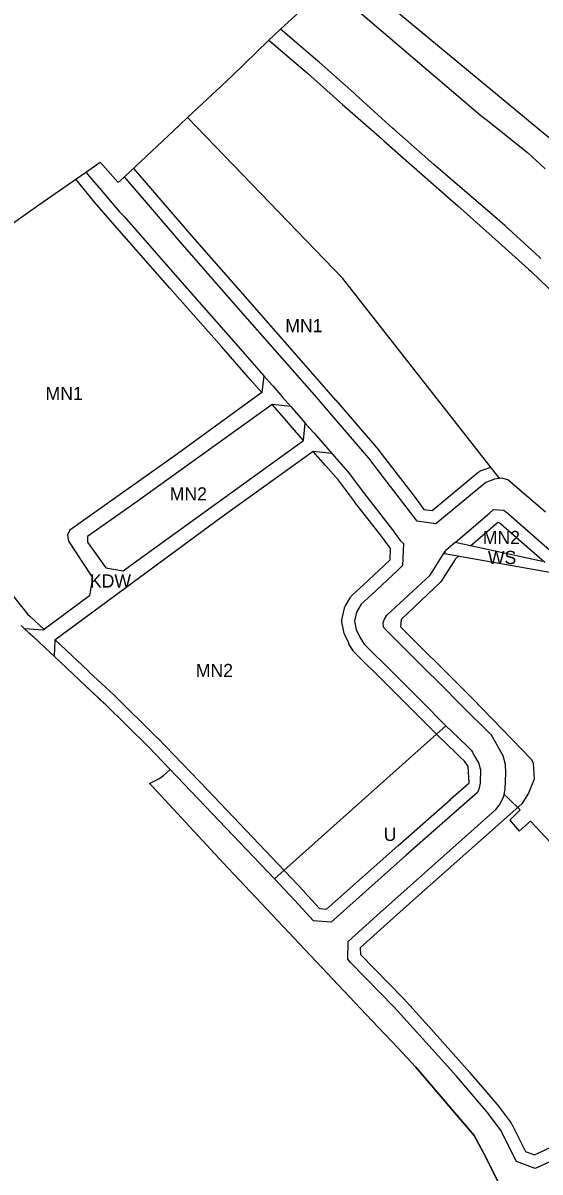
# Model space of a CAD drawing. Extents: x 7435758 to 7439981, y 5550649 to 5554049.
# Drawn here: x 7436617.4 to 7436821.5, y 5551911.1 to 5552364.7 of the extents above; entities that cross this region are included whole.
import ezdxf

# ---------------------------------------------------------------- set-up
doc = ezdxf.new("R2010")
doc.units = 0
for name, color, linetype in [('_Tereny dla których obowiązuje MPZP', 7, 'Continuous'), ('linie_rozgraniczające', 7, 'Continuous'), ('linie_zabudowy_nieprzekraczalne', 7, 'Continuous'), ('oznaczenia_przeznaczen', 7, 'Continuous')]:
    doc.layers.add(name, color=color, linetype=linetype)

msp = doc.modelspace()

# ---------------------------------------------------------------- linework, layer by layer
at = {"layer": '_Tereny dla których obowiązuje MPZP'}
for p, q in [((7436618.09, 5552125.56), (7436616.77, 5552126.8)), ((7436626.04, 5552118.11), (7436621.66, 5552122.21)), ((7436675.53, 5552070.02), (7436666.93, 5552078.97)), ((7436667.4, 5552064.42), (7436670.98, 5552066.27)), ((7436787.1, 5551935.35), (7436772.47, 5551952.52)), ((7436795.43, 5551925.58), (7436787.1, 5551935.35)), ((7436800.14, 5551917.03), (7436795.43, 5551925.58)), ((7436805.8, 5551905.51), (7436800.14, 5551917.03))]:
    msp.add_line(p, q, dxfattribs=at)
for points in [[(7436621.66, 5552122.21), (7436621.35, 5552122.5), (7436618.09, 5552125.56)], [(7436639.76, 5552105.23), (7436629.69, 5552114.68), (7436626.04, 5552118.11)], [(7436666.93, 5552078.97), (7436649.86, 5552095.77), (7436649.52, 5552096.09), (7436639.76, 5552105.23)], [(7436670.98, 5552066.27), (7436672.93, 5552067.67), (7436675.53, 5552070.02)], [(7436772.47, 5551952.52), (7436765.31, 5551960.09), (7436755.06, 5551970.94), (7436728.65, 5551998.96), (7436696.39, 5552033.17), (7436668.52, 5552063.33), (7436667.4, 5552064.42)]]:
    msp.add_lwpolyline(points, dxfattribs=at)
at = {"layer": 'linie_rozgraniczające'}
for p, q in [((7436737.83, 5552379.62), (7436798.12, 5552328.15)), ((7436719, 5552362.18), (7436734.94, 5552376.74)), ((7436828.32, 5552316.54), (7436754.67, 5552377.68)), ((7436714.41, 5552357.83), (7436719, 5552362.18)), ((7436733.68, 5552349.73), (7436719, 5552362.18)), ((7436699.7, 5552343.51), (7436714.41, 5552357.83)), ((7436714.41, 5552357.83), (7436729.68, 5552344.79)), ((7436734.36, 5552349.15), (7436733.68, 5552349.73)), ((7436748.06, 5552337.04), (7436734.36, 5552349.15)), ((7436682.42, 5552327.36), (7436699.7, 5552343.51)), ((7436729.68, 5552344.79), (7436741.13, 5552334.61)), ((7436741.13, 5552334.61), (7436743.48, 5552332.53)), ((7436748.82, 5552336.34), (7436748.06, 5552337.04)), ((7436763.28, 5552323.19), (7436748.82, 5552336.34)), ((7436743.48, 5552332.53), (7436758.9, 5552319)), ((7436679.35, 5552324.5), (7436682.42, 5552327.36)), ((7436743.6, 5552263.84), (7436682.42, 5552327.36)), ((7436798.12, 5552328.15), (7436800.78, 5552326.16)), ((7436800.78, 5552326.16), (7436816.7, 5552313.41)), ((7436674.72, 5552320.14), (7436679.35, 5552324.5)), ((7436763.78, 5552322.75), (7436763.28, 5552323.19)), ((7436779.47, 5552308.86), (7436763.78, 5552322.75)), ((7436657.44, 5552303.88), (7436674.72, 5552320.14)), ((7436758.9, 5552319), (7436759.8, 5552318.19)), ((7436759.8, 5552318.19), (7436775.04, 5552304.67)), ((7436816.7, 5552313.41), (7436823.53, 5552307.12)), ((7436642.21, 5552305.72), (7436644.29, 5552307.18)), ((7436644.29, 5552307.18), (7436647.88, 5552309.69)), ((7436647.88, 5552309.69), (7436655.06, 5552301.64)), ((7436793.58, 5552296.81), (7436779.47, 5552308.86)), ((7436623.75, 5552292.81), (7436641.77, 5552305.41)), ((7436641.77, 5552305.41), (7436642.21, 5552305.72)), ((7436642.21, 5552305.72), (7436645.04, 5552302.41)), ((7436655.06, 5552301.64), (7436657.17, 5552303.63)), ((7436657.17, 5552303.63), (7436657.44, 5552303.88)), ((7436680.33, 5552277.2), (7436657.44, 5552303.88)), ((7436775.04, 5552304.67), (7436789.02, 5552292.46)), ((7436645.04, 5552302.41), (7436648.3, 5552298.6)), ((7436648.3, 5552298.6), (7436655.54, 5552290.15)), ((7436802.59, 5552289.01), (7436793.58, 5552296.81)), ((7436601.5, 5552277.15), (7436623.75, 5552292.81)), ((7436655.54, 5552290.15), (7436657.3, 5552288.2)), ((7436789.02, 5552292.46), (7436802.61, 5552280.39)), ((7436807.58, 5552284.69), (7436802.59, 5552289.01)), ((7436657.3, 5552288.2), (7436679.16, 5552263.3)), ((7436821.22, 5552272.23), (7436807.58, 5552284.69)), ((7436802.61, 5552280.39), (7436805.12, 5552278.15)), ((7436703.17, 5552251.13), (7436680.33, 5552277.2)), ((7436805.12, 5552278.15), (7436816.98, 5552267.53)), ((7436821.84, 5552271.66), (7436821.22, 5552272.23)), ((7436816.98, 5552267.53), (7436817.87, 5552266.67)), ((7436817.87, 5552266.67), (7436831.59, 5552253.59)), ((7436679.16, 5552263.3), (7436699.47, 5552240.22)), ((7436805.24, 5552185.29), (7436743.6, 5552263.84)), ((7436733.34, 5552216.78), (7436703.17, 5552251.13)), ((7436699.47, 5552240.22), (7436712.48, 5552225.41)), ((7436712.48, 5552225.41), (7436711.75, 5552218.76)), ((7436712.48, 5552225.41), (7436715.76, 5552221.66)), ((7436715.76, 5552221.66), (7436716.11, 5552221.27)), ((7436716.11, 5552221.27), (7436719.82, 5552217.01)), ((7436711.75, 5552218.76), (7436677.43, 5552193.95)), ((7436719.82, 5552217.01), (7436723.1, 5552213.23)), ((7436737.06, 5552212.54), (7436733.34, 5552216.78)), ((7436715.79, 5552214.12), (7436661.52, 5552175.12)), ((7436723.1, 5552213.23), (7436715.79, 5552214.12)), ((7436723.1, 5552213.23), (7436725.32, 5552210.68)), ((7436753.92, 5552192.88), (7436737.06, 5552212.54)), ((7436725.32, 5552210.68), (7436728.82, 5552206.65)), ((7436728.08, 5552199.9), (7436728.82, 5552206.65)), ((7436728.82, 5552206.65), (7436729.22, 5552206.19)), ((7436729.22, 5552206.19), (7436732.16, 5552202.85)), ((7436732.16, 5552202.85), (7436736, 5552198.47)), ((7436660.97, 5552151.35), (7436728.08, 5552199.9)), ((7436736, 5552198.47), (7436739.31, 5552194.7)), ((7436677.43, 5552193.95), (7436635.93, 5552164.48)), ((7436731.96, 5552195.55), (7436696.1, 5552169.7)), ((7436739.31, 5552194.7), (7436731.96, 5552195.55)), ((7436739.31, 5552194.7), (7436745.79, 5552187.3)), ((7436759.87, 5552185.15), (7436753.92, 5552192.88)), ((7436745.79, 5552187.3), (7436752.23, 5552178.76)), ((7436767.8, 5552174.85), (7436759.87, 5552185.15)), ((7436803.46, 5552184.56), (7436800.11, 5552183.31)), ((7436805.53, 5552184.85), (7436803.46, 5552184.56)), ((7436805.53, 5552184.85), (7436805.24, 5552185.29)), ((7436806.41, 5552184.97), (7436805.53, 5552184.85)), ((7436808.74, 5552184.32), (7436806.41, 5552184.97)), ((7436800.11, 5552183.31), (7436780.41, 5552166.99)), ((7436823.61, 5552171.62), (7436808.74, 5552184.32)), ((7436752.23, 5552178.76), (7436763.23, 5552164.63)), ((7436661.52, 5552175.12), (7436642.85, 5552161.98)), ((7436773.01, 5552167.95), (7436767.8, 5552174.85)), ((7436787.94, 5552159.56), (7436801.5, 5552171.12)), ((7436801.5, 5552171.12), (7436803.17, 5552172.56)), ((7436803.17, 5552172.56), (7436807.16, 5552172.31)), ((7436807.16, 5552172.31), (7436809.23, 5552170.75)), ((7436696.1, 5552169.7), (7436630.03, 5552121.05)), ((7436780.41, 5552166.99), (7436773.01, 5552167.95)), ((7436809.23, 5552170.75), (7436828.55, 5552153.85)), ((7436635.93, 5552164.48), (7436635, 5552162.42)), ((7436635, 5552162.42), (7436635.35, 5552160.16)), ((7436642.85, 5552161.98), (7436642.95, 5552159.71)), ((7436763.23, 5552164.63), (7436766.33, 5552160.44)), ((7436635.35, 5552160.16), (7436644.23, 5552146.63)), ((7436642.95, 5552159.71), (7436650.07, 5552149.53)), ((7436766.33, 5552160.44), (7436767.54, 5552159.15)), ((7436767.54, 5552159.15), (7436767.27, 5552150.48)), ((7436787.94, 5552159.56), (7436784.31, 5552156.47)), ((7436822.42, 5552152.11), (7436787.94, 5552159.56)), ((7436778.08, 5552146.7), (7436784.08, 5552156.11)), ((7436784.08, 5552156.11), (7436783.84, 5552155.27)), ((7436783.84, 5552155.27), (7436831.22, 5552146.85)), ((7436784.31, 5552156.47), (7436784.08, 5552156.11)), ((7436650.07, 5552149.53), (7436657, 5552148.41)), ((7436657, 5552148.41), (7436660.97, 5552151.35)), ((7436765.31, 5552148.66), (7436754.95, 5552138.9)), ((7436767.27, 5552150.48), (7436765.31, 5552148.66)), ((7436644.88, 5552145.67), (7436643.71, 5552138.56)), ((7436644.23, 5552146.63), (7436644.88, 5552145.67)), ((7436760.97, 5552130.85), (7436778.08, 5552146.7)), ((7436643.71, 5552138.56), (7436625.44, 5552125.01)), ((7436750.88, 5552135.3), (7436749.07, 5552132.12)), ((7436754.95, 5552138.9), (7436750.88, 5552135.3)), ((7436749.07, 5552132.12), (7436748.31, 5552128.59)), ((7436760.13, 5552129.39), (7436760.97, 5552130.85)), ((7436618.09, 5552125.56), (7436616.77, 5552126.8)), ((7436618.09, 5552125.56), (7436616.77, 5552126.8)), ((7436621.66, 5552122.21), (7436618.09, 5552125.56)), ((7436625.44, 5552125.01), (7436618.09, 5552125.56)), ((7436748.31, 5552128.59), (7436748.96, 5552125.25)), ((7436759.53, 5552128.07), (7436760.13, 5552129.39)), ((7436759.74, 5552126.14), (7436759.53, 5552128.07)), ((7436760.83, 5552124.89), (7436759.74, 5552126.14)), ((7436626.04, 5552118.11), (7436621.66, 5552122.21)), ((7436626.04, 5552118.11), (7436621.66, 5552122.21)), ((7436630.03, 5552121.05), (7436629.69, 5552114.68)), ((7436748.96, 5552125.25), (7436750.38, 5552122.19)), ((7436750.38, 5552122.19), (7436752.05, 5552119.41)), ((7436775.75, 5552110.01), (7436760.83, 5552124.89)), ((7436629.69, 5552114.68), (7436626.04, 5552118.11)), ((7436752.05, 5552119.41), (7436763.65, 5552107.96)), ((7436639.76, 5552105.23), (7436629.69, 5552114.68)), ((7436763.65, 5552107.96), (7436774.86, 5552096.77)), ((7436782.28, 5552103.48), (7436775.75, 5552110.01)), ((7436649.86, 5552095.77), (7436639.76, 5552105.23)), ((7436790.2, 5552095.57), (7436782.28, 5552103.48)), ((7436666.93, 5552078.97), (7436649.86, 5552095.77)), ((7436774.86, 5552096.77), (7436784.37, 5552087.28)), ((7436802.37, 5552083.59), (7436790.2, 5552095.57)), ((7436761.03, 5552066.45), (7436784.37, 5552087.28)), ((7436784.37, 5552087.28), (7436786.4, 5552085.24)), ((7436786.4, 5552085.24), (7436792.76, 5552079.14)), ((7436806.91, 5552075.42), (7436802.37, 5552083.59)), ((7436686.62, 5552058.46), (7436666.93, 5552078.97)), ((7436675.53, 5552070.02), (7436666.93, 5552078.97)), ((7436792.76, 5552079.14), (7436794.29, 5552077.67)), ((7436794.29, 5552077.67), (7436794.8, 5552076.77)), ((7436794.8, 5552076.77), (7436795.27, 5552075.92)), ((7436795.27, 5552075.92), (7436795.86, 5552074.86)), ((7436795.86, 5552074.86), (7436797.31, 5552072.31)), ((7436797.31, 5552072.31), (7436797.78, 5552070.66)), ((7436807.88, 5552072.02), (7436806.91, 5552075.42)), ((7436807.98, 5552068.59), (7436807.88, 5552072.02)), ((7436797.78, 5552070.66), (7436797.97, 5552069.97)), ((7436797.97, 5552069.97), (7436797.81, 5552064.61)), ((7436807.76, 5552062.36), (7436807.98, 5552068.59)), ((7436667.4, 5552064.42), (7436670.98, 5552066.27)), ((7436716.64, 5552026.84), (7436761.03, 5552066.45)), ((7436797.37, 5552062.16), (7436796.78, 5552060.93)), ((7436797.81, 5552064.61), (7436797.37, 5552062.16)), ((7436807.27, 5552060.18), (7436807.76, 5552062.36)), ((7436716.64, 5552026.84), (7436686.62, 5552058.46)), ((7436796.78, 5552060.93), (7436789.4, 5552054.47)), ((7436805.46, 5552056.09), (7436807.03, 5552059.11)), ((7436807.03, 5552059.11), (7436807.27, 5552060.18)), ((7436807.27, 5552060.18), (7436809.01, 5552058.5)), ((7436809.01, 5552058.5), (7436813.62, 5552054.07)), ((7436756.98, 5552012.28), (7436804.1, 5552054.14)), ((7436789.4, 5552054.47), (7436768.64, 5552036.13)), ((7436804.1, 5552054.14), (7436805.46, 5552056.09)), ((7436813.62, 5552054.07), (7436809.59, 5552049.96)), ((7436809.59, 5552049.96), (7436813.22, 5552045.67)), ((7436813.22, 5552045.67), (7436817.74, 5552049.55)), ((7436817.74, 5552049.55), (7436832.43, 5552033.88)), ((7436768.64, 5552036.13), (7436739.01, 5552009.68)), ((7436724.72, 5552018.34), (7436716.64, 5552026.84)), ((7436732.02, 5552010.27), (7436724.72, 5552018.34)), ((7436745.81, 5552002.16), (7436756.98, 5552012.28)), ((7436739.01, 5552009.68), (7436732.02, 5552010.27)), ((7436728.65, 5551998.96), (7436755.06, 5551970.94)), ((7436745.58, 5551995.13), (7436745.81, 5552002.16)), ((7436746.75, 5551993.82), (7436745.58, 5551995.13)), ((7436763.86, 5551976.21), (7436746.75, 5551993.82)), ((7436773.94, 5551965.1), (7436763.86, 5551976.21)), ((7436755.06, 5551970.94), (7436765.31, 5551960.09)), ((7436778.9, 5551959.57), (7436773.94, 5551965.1)), ((7436765.31, 5551960.09), (7436772.47, 5551952.52)), ((7436788.47, 5551948.91), (7436778.9, 5551959.57)), ((7436772.47, 5551952.52), (7436787.1, 5551935.35)), ((7436787.1, 5551935.35), (7436772.47, 5551952.52)), ((7436800.66, 5551934.67), (7436788.47, 5551948.91)), ((7436787.1, 5551935.35), (7436795.43, 5551925.58)), ((7436795.43, 5551925.58), (7436787.1, 5551935.35)), ((7436805.86, 5551927.78), (7436800.66, 5551934.67)), ((7436868.15, 5551934.9), (7436819.57, 5551912.53)), ((7436812.2, 5551915.2), (7436805.86, 5551927.78)), ((7436795.43, 5551925.58), (7436800.14, 5551917.03)), ((7436800.14, 5551917.03), (7436795.43, 5551925.58)), ((7436800.14, 5551917.03), (7436805.8, 5551905.51)), ((7436805.8, 5551905.51), (7436800.14, 5551917.03)), ((7436819.57, 5551912.53), (7436812.2, 5551915.2))]:
    msp.add_line(p, q, dxfattribs=at)
for points in [[(7436621.66, 5552122.21), (7436621.35, 5552122.5), (7436618.09, 5552125.56)], [(7436639.76, 5552105.23), (7436629.69, 5552114.68), (7436626.04, 5552118.11)], [(7436666.93, 5552078.97), (7436649.86, 5552095.77), (7436649.52, 5552096.09), (7436639.76, 5552105.23)], [(7436670.98, 5552066.27), (7436672.93, 5552067.67), (7436675.53, 5552070.02)], [(7436772.47, 5551952.52), (7436765.31, 5551960.09), (7436755.06, 5551970.94), (7436728.65, 5551998.96), (7436696.39, 5552033.17), (7436668.52, 5552063.33), (7436667.4, 5552064.42)]]:
    msp.add_lwpolyline(points, dxfattribs=at)
at = {"layer": 'linie_zabudowy_nieprzekraczalne'}
for points in [[(7436661.08, 5552307.31), (7436661.24, 5552307.14), (7436684.11, 5552280.48), (7436706.93, 5552254.42), (7436740.82, 5552215.83), (7436740.86, 5552215.79), (7436757.72, 5552196.14), (7436757.76, 5552196.08), (7436757.88, 5552195.93), (7436771.77, 5552177.9), (7436771.8, 5552177.86), (7436775.61, 5552172.65), (7436778.9, 5552172.22), (7436796.92, 5552187.16), (7436797.17, 5552187.35), (7436797.44, 5552187.54), (7436797.72, 5552187.7), (7436798.01, 5552187.85), (7436798.31, 5552187.98), (7436798.37, 5552188), (7436801.72, 5552189.24), (7436801.98, 5552189.33), (7436802.01, 5552189.34)], [(7436711.75, 5552218.76), (7436707.27, 5552223.76), (7436695.71, 5552236.92), (7436675.41, 5552260), (7436675.41, 5552260), (7436653.56, 5552284.88), (7436651.83, 5552286.8), (7436651.74, 5552286.89), (7436645.84, 5552293.79), (7436638.33, 5552303.05)], [(7436552.58, 5552242.96), (7436559.84, 5552232.12), (7436559.91, 5552232.01), (7436560.08, 5552231.73), (7436560.08, 5552231.72), (7436566.5, 5552219.83), (7436566.62, 5552219.61), (7436571.73, 5552208.89), (7436578.78, 5552194.36), (7436585.94, 5552180.53), (7436594.39, 5552165.14), (7436604.07, 5552150.69), (7436611.91, 5552140.64), (7436619.4, 5552131.18), (7436620.16, 5552130.48), (7436620.19, 5552130.45), (7436625.76, 5552125.22)], [(7436728.08, 5552199.9), (7436723.62, 5552205.02), (7436720.59, 5552208.5), (7436715.79, 5552214.12)], [(7436630.15, 5552121.11), (7436643.19, 5552108.88), (7436643.39, 5552108.68), (7436643.61, 5552108.44), (7436653.28, 5552099.41), (7436653.36, 5552099.33), (7436670.44, 5552082.54), (7436670.54, 5552082.43), (7436690.22, 5552061.92), (7436690.24, 5552061.91), (7436690.24, 5552061.9), (7436728.35, 5552021.78), (7436728.43, 5552021.69), (7436734.4, 5552015.09), (7436737.28, 5552014.85), (7436765.31, 5552039.86), (7436765.33, 5552039.88), (7436786.09, 5552058.21), (7436786.11, 5552058.23), (7436793.42, 5552064.62), (7436793.5, 5552064.7), (7436793.24, 5552069.11), (7436793.16, 5552071.21), (7436791.68, 5552073.24), (7436789.82, 5552075.03), (7436782.94, 5552081.64), (7436782.87, 5552081.71), (7436760.13, 5552104.42), (7436748.54, 5552115.85), (7436748.42, 5552115.97), (7436748.21, 5552116.21), (7436748.01, 5552116.47), (7436747.82, 5552116.74), (7436747.76, 5552116.84), (7436746.09, 5552119.62), (7436745.99, 5552119.8), (7436745.85, 5552120.09), (7436744.43, 5552123.14), (7436744.42, 5552123.15), (7436744.29, 5552123.45), (7436744.19, 5552123.76), (7436744.1, 5552124.07), (7436744.05, 5552124.29), (7436743.4, 5552127.63), (7436743.38, 5552127.73), (7436743.33, 5552128.06), (7436743.31, 5552128.38), (7436743.31, 5552128.71), (7436743.33, 5552129.04), (7436743.37, 5552129.36), (7436743.42, 5552129.65), (7436744.18, 5552133.17), (7436744.19, 5552133.21), (7436744.27, 5552133.53), (7436744.38, 5552133.84), (7436744.5, 5552134.14), (7436744.64, 5552134.44), (7436744.73, 5552134.59), (7436746.54, 5552137.78), (7436746.62, 5552137.91), (7436746.8, 5552138.18), (7436746.99, 5552138.44), (7436747.21, 5552138.69), (7436747.44, 5552138.92), (7436747.57, 5552139.04), (7436751.58, 5552142.59), (7436762.34, 5552152.73), (7436762.48, 5552157.25), (7436759.25, 5552161.6), (7436748.28, 5552175.68), (7436748.24, 5552175.75), (7436741.91, 5552184.15), (7436736.82, 5552189.95), (7436731.96, 5552195.55)], [(7436823.4, 5552151.73), (7436806.07, 5552166.86), (7436805.35, 5552167.41), (7436804.89, 5552167.44), (7436804.77, 5552167.34), (7436804.75, 5552167.31), (7436794.03, 5552158.09)], [(7436789.3, 5552154.17), (7436788.15, 5552153.19), (7436782.3, 5552144.01), (7436766.67, 5552129.2), (7436766.39, 5552126.3), (7436773.23, 5552119.5), (7436784.38, 5552108.4), (7436794.83, 5552098.03), (7436818.07, 5552073.98), (7436818.76, 5552072.52), (7436819.15, 5552066.18), (7436816.99, 5552060.66), (7436814.25, 5552056.45), (7436771.3, 5552018.3), (7436757.24, 5552005.64), (7436750.48, 5551999.55), (7436750.64, 5551996.99), (7436767.45, 5551979.69), (7436767.48, 5551979.66), (7436767.56, 5551979.57), (7436776.31, 5551970), (7436776.51, 5551969.78), (7436793.62, 5551950.58), (7436794.11, 5551950.01), (7436804.46, 5551937.92), (7436804.5, 5551937.87), (7436804.65, 5551937.68), (7436809.85, 5551930.79), (7436809.9, 5551930.72), (7436810.08, 5551930.45), (7436810.25, 5551930.17), (7436810.32, 5551930.03), (7436815.77, 5551919.23), (7436819.34, 5551917.93), (7436866.06, 5551939.44)], [(7436793.62, 5551950.58), (7436793.61, 5551950.44)]]:
    msp.add_lwpolyline(points, dxfattribs=at)

# ---------------------------------------------------------------- texts
at = {"layer": 'oznaczenia_przeznaczen'}
for s, p in [('MN1', (7436720.95, 5552242.58)), ('MN1', (7436626.35, 5552215.82)), ('MN2', (7436675.35, 5552176.17)), ('MN2', (7436798.88, 5552158.98)), ('WS', (7436800.9, 5552151.08)), ('KDW', (7436643.85, 5552141.81)), ('MN2', (7436685.63, 5552106.48)), ('U', (7436759.8, 5552041.78))]:
    msp.add_text(s, height=5.2, dxfattribs=at).set_placement(p)

doc.saveas('drawing.dxf')
